// Mitsubishi GX Works2 project: MC-12MR-8MTS-F700-FX2N-C   PLC: FX2N/FX2NC

PROGRAM MAIN
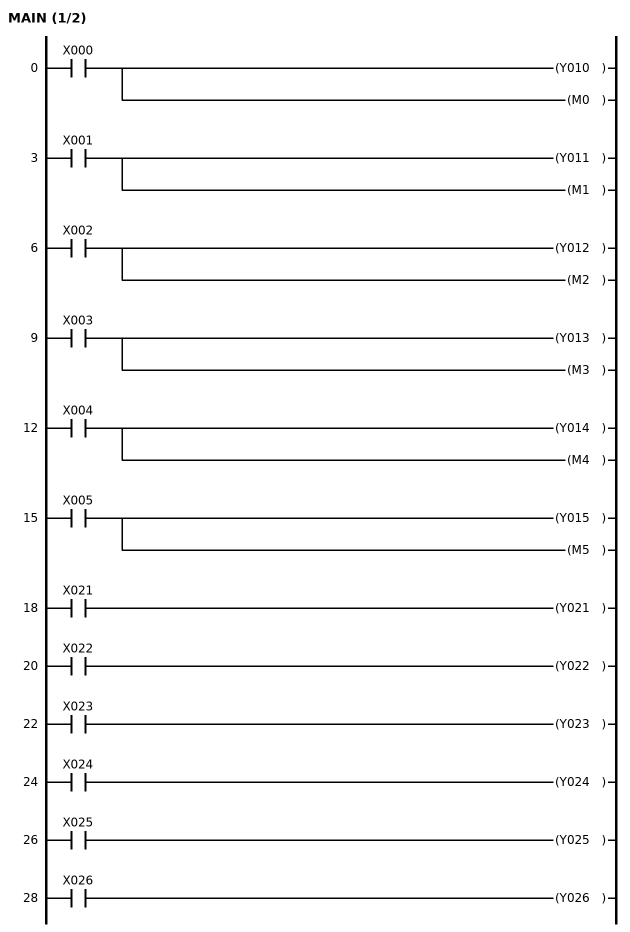
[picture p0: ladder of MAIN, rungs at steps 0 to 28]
0     LD      X000
      OUT     Y010
      OUT     M0
3     LD      X001
      OUT     Y011
      OUT     M1
6     LD      X002
      OUT     Y012
      OUT     M2
9     LD      X003
      OUT     Y013
      OUT     M3
12    LD      X004
      OUT     Y014
      OUT     M4
15    LD      X005
      OUT     Y015
      OUT     M5
18    LD      X021
      OUT     Y021
20    LD      X022
      OUT     Y022
22    LD      X023
      OUT     Y023
24    LD      X024
      OUT     Y024
26    LD      X025
      OUT     Y025
28    LD      X026
      OUT     Y026
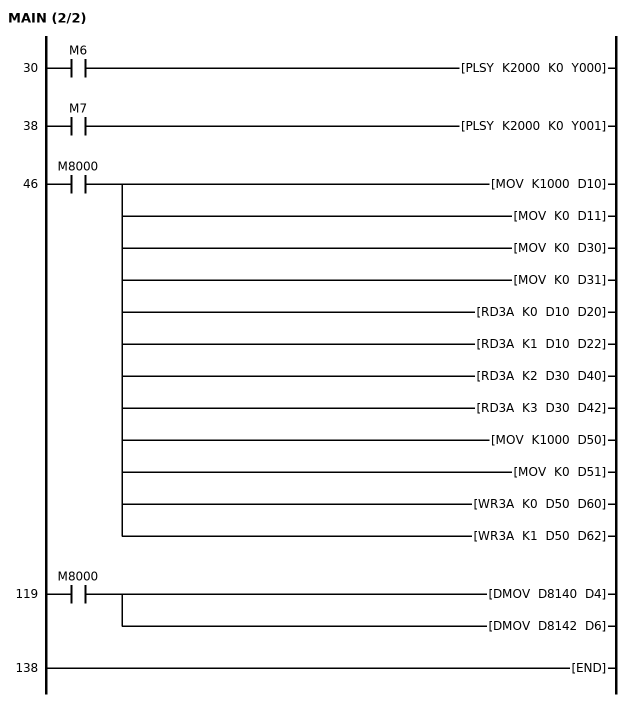
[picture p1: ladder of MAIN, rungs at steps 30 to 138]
30    LD      M6
      PLSY    K2000 K0 Y000
38    LD      M7
      PLSY    K2000 K0 Y001
46    LD      M8000
      MOV     K1000 D10
      MOV     K0 D11
      MOV     K0 D30
      MOV     K0 D31
      RD3A    K0 D10 D20
      RD3A    K1 D10 D22
      RD3A    K2 D30 D40
      RD3A    K3 D30 D42
      MOV     K1000 D50
      MOV     K0 D51
      WR3A    K0 D50 D60
      WR3A    K1 D50 D62
119   LD      M8000
      DMOV    D8140 D4
      DMOV    D8142 D6
138   END
END_PROGRAM
